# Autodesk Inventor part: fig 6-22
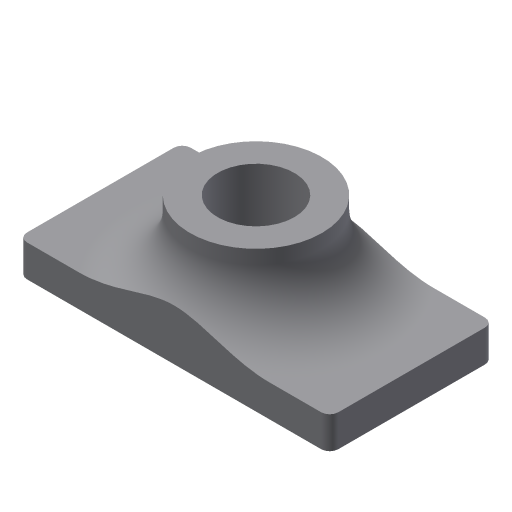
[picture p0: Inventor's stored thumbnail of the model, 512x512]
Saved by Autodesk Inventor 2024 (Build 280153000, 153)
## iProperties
Created: 2004-05
Part Number: fig 6-22
Document SubType Name: Modeling
Designer: CADCIM Technologies
Manufacturer: Standard
Standards Organization: Custom
Density: 1 g/cm^3
Material: Generic
Appearance: Default
Author: CADCIM Technologies
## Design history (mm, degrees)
sketch "Sketch1"
  geometry: L1 (-39.276, -18.692)-(33.721, -18.692); L2 (33.721, -18.692)-(33.721, 19.728); L3 (33.721, 19.728)-(-39.276, 19.728); L4 (-39.276, 19.728)-(-39.276, -18.692)
  constraints: 8 end point, 2 parallel, 1 horizontal, 1 perpendicular
extrude "Extrusion1" new body sketch "Sketch1" distance "d0" = 7.5; taper "d1" = 0 deg
fillet "Fillet1" dims "d2" = 2
sketch "Sketch2"
  geometry: C1 r 15.456 at (-2.778, 0.518)
  constraints: 1 centre point
extrude "Extrusion2" join sketch "Sketch2" distance "d3" = 17.25; taper "d4" = 0 deg
hole "Hole1" diameter "d8" = 18; stored, may be unused: countersink angle "d12" = 90 deg, drill point angle "d14" = 118 deg; dims "d6" = 10, "d7" = 10, "d9" = 6, "d10" = 4, "d11" = 2, "d13" = 8
fillet "Fillet2" dims "d5" = 14
body "Solid1"
